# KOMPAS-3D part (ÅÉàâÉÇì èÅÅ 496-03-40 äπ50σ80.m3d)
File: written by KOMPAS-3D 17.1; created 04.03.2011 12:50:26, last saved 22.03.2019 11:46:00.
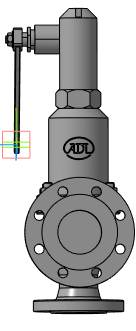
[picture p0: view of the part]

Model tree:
1. Операция без истории:1

Referenced files in C:\Users\tra\Desktop\Детали с марк. для Сферы\bsv\Desktop\Si 57\: VIC_496_50x80_3d.a3d
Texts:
  Viktor2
